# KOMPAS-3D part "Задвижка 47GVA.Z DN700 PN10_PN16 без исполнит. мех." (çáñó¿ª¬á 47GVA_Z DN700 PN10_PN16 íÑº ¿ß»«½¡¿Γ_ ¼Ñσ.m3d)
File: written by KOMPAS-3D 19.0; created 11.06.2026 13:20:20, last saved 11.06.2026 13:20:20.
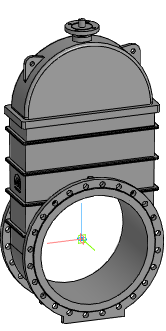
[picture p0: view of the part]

Document properties: Автор: Евгений; Полное имя файла: Z:\3.Личные\kachalov\001_3d для проектировщиков\2.2 Тип 47GVA, 47GVA.Z\_stp\_stp_Задвижка 47GVA.Z DN350-DN1200 без исп.мех\Задвижка 47GVA_Z DN700 PN10_PN16 без исполнит_ мех.m3d

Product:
- Part/product: Задвижка 47GVA.Z DN700 PN10_PN16 без исполнит. мех.

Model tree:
1. Операция без истории:1  (labels: Задвижка 47GVA.Z DN700 PN10_PN16 без исполнит. мех.)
